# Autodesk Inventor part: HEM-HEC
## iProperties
Author: Jan-Steinar
Shininess: 20.0
PropertySet Name: _Private Model Information
Created: 2001-01
Part Number: HEM-HEC
Document SubType Name: Modeling
Designer: Jan-Steinar
Control State: 0
Master: False
Checked Out: False
PropertySet Name: Design Tracking Control
Density: 0.0
Volumn: 0.0
Area: 0.0
PropertySet Name: Model Information
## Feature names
1. Extrusion1
